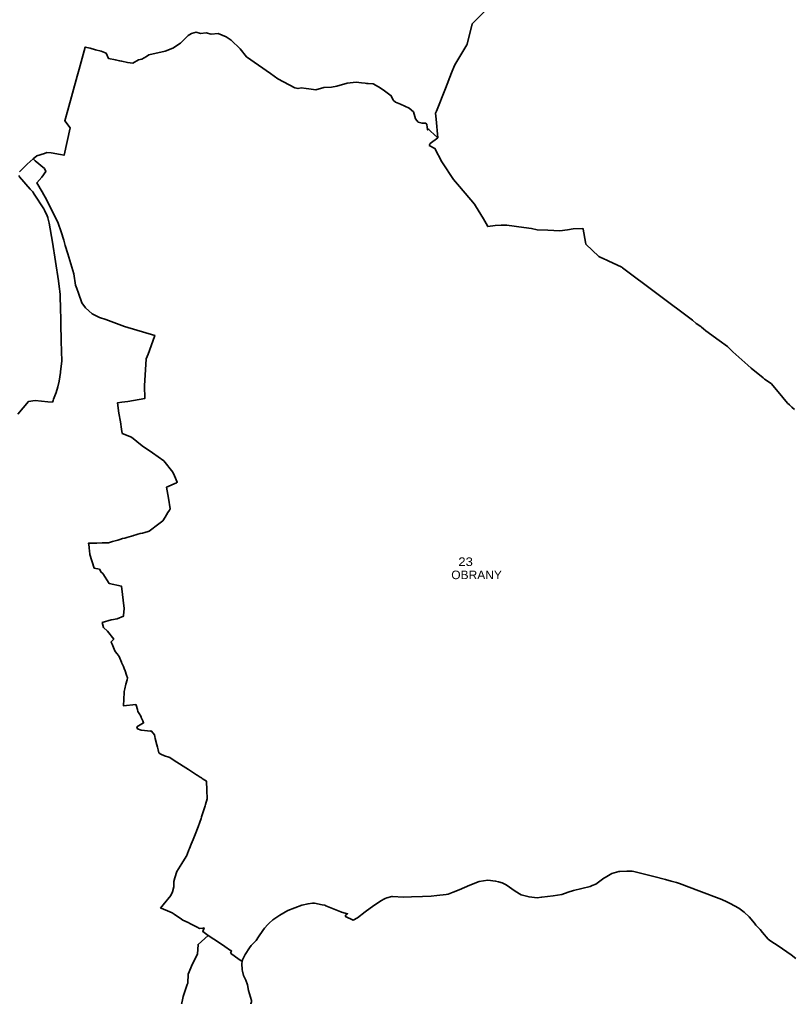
# Model space of a CAD drawing. Extents: x -610940 to -588976, y -1170376 to -1149800.
# Drawn here: x -596331 to -594068, y -1157762 to -1154902 of the extents above; entities that cross this region are included whole.
import ezdxf

# ---------------------------------------------------------------- set-up
doc = ezdxf.new("R2010")
doc.units = 0
doc.header["$LTSCALE"] = 10
doc.layers.add('54', color=7, linetype='Continuous', lineweight=35)
doc.layers.add('55', color=7, linetype='Continuous')
doc.layers.add('56', color=7, linetype='Continuous')

msp = doc.modelspace()

# ---------------------------------------------------------------- linework, layer by layer
at = {"layer": '54'}
for p, q in [((-595762.41, -1157594.1), (-595748.67, -1157602.84)), ((-595713.84, -1157635.74), (-595688.28, -1157653.39)), ((-595712.92, -1157627.4), (-595712.15, -1157627.92)), ((-595712.15, -1157627.92), (-595709.55, -1157629.68)), ((-595688.28, -1157653.39), (-595682.9, -1157657.14)), ((-595840.03, -1157727.17), (-595838.51, -1157722.82))]:
    msp.add_line(p, q, dxfattribs=at)
for points in [[(-594622.71, -1154865.58), (-594646.74, -1154867.4), (-594653.7, -1154868.08), (-594663.98, -1154853.48), (-594711.65, -1154816.59), (-594781.77, -1154806.74), (-594846.26, -1154824.79), (-594858.48, -1154826.3), (-594863.26, -1154826.82), (-594903.94, -1154831.02), (-594929.78, -1154848.3), (-594932.22, -1154849.74), (-594956.48, -1154865.5), (-595005.69, -1154915.44), (-595020.68, -1154974.54), (-595021.77, -1154976.36), (-595054.03, -1155029.88), (-595058.01, -1155036.7), (-595066.38, -1155058.3), (-595084.21, -1155104.14), (-595110.63, -1155170.57), (-595112.96, -1155176.16), (-595111.29, -1155193.92), (-595106.51, -1155248.2)], [(-596291.2, -1155310.54), (-596280.54, -1155301.63), (-596258.1, -1155294.06), (-596251.39, -1155292.04), (-596238.55, -1155292.99), (-596211.27, -1155297.54), (-596200.37, -1155299.52), (-596182.3, -1155219.38), (-596198.45, -1155198.44), (-596189.99, -1155167.8), (-596162.57, -1155068.28), (-596156.82, -1155047.96), (-596138.47, -1154982.87), (-596124.3, -1154986.33), (-596108.39, -1154990.68), (-596091.89, -1154995.25), (-596077.47, -1155000.86), (-596070.23, -1155016.7), (-596050.36, -1155020.63), (-596038.12, -1155023.05), (-596031.81, -1155024.45), (-596015.28, -1155028.11), (-595999.14, -1155029.96), (-595982.56, -1155020.84), (-595973.11, -1155018.42), (-595959.43, -1155010.19), (-595952.03, -1155005.78), (-595904.23, -1154995.31), (-595882.14, -1154985.89), (-595859.81, -1154971.63), (-595837.26, -1154948.82), (-595827.09, -1154943.49), (-595813.62, -1154939.23), (-595801.5, -1154943.07), (-595784.24, -1154941.5), (-595769.85, -1154945.18), (-595749.95, -1154943.61), (-595726.33, -1154952.78), (-595711.33, -1154962.31), (-595684.95, -1154987.68)], [(-595684.95, -1154987.68), (-595666.32, -1155011.48), (-595596.6, -1155060.17), (-595574.65, -1155075.7), (-595524.52, -1155102.28), (-595515.65, -1155104.45), (-595506.9, -1155102.74), (-595492.23, -1155103.97), (-595483.78, -1155104.78), (-595463.07, -1155107.98), (-595439.65, -1155101.6), (-595417.28, -1155100.35), (-595402.11, -1155097.01), (-595372.16, -1155088.26), (-595345.87, -1155085.3), (-595329.84, -1155087.61), (-595319.12, -1155089.09), (-595315.54, -1155089.38), (-595310.33, -1155089.63), (-595296, -1155090.79), (-595279.87, -1155099.66), (-595266.83, -1155108.52), (-595242.76, -1155125.34), (-595237.14, -1155138.13), (-595229.82, -1155144.12), (-595216.12, -1155149.68), (-595190.08, -1155162.28), (-595177.37, -1155172.69), (-595171.75, -1155193.4), (-595163.72, -1155202.58), (-595152.3, -1155206.04), (-595141.63, -1155205.77), (-595138.14, -1155209.53), (-595136.34, -1155225.45), (-595134.34, -1155223), (-595132.98, -1155223.93), (-595127.53, -1155228.87), (-595106.51, -1155248.2), (-595129.01, -1155265.67), (-595131.41, -1155270.88)], [(-595131.41, -1155270.88), (-595114.84, -1155279.7), (-595094.36, -1155318.81), (-595092.64, -1155321.94), (-595060.21, -1155371.01), (-595042.84, -1155391.16), (-594999.33, -1155442.6), (-594996.07, -1155447.63), (-594972.71, -1155485.6), (-594961.1, -1155506.62), (-594960.57, -1155508.2), (-594960.34, -1155508.16), (-594938.14, -1155504.89), (-594921.27, -1155504.46), (-594904.71, -1155504.27), (-594854.2, -1155511.28), (-594831.9, -1155514.3), (-594815.28, -1155517.66), (-594784.75, -1155519.37), (-594749.59, -1155520.83), (-594726.53, -1155517.84), (-594710.55, -1155515.48), (-594681.56, -1155514.41), (-594681.2, -1155516.39), (-594674.37, -1155554.04), (-594673.17, -1155559.9), (-594635.12, -1155596.05), (-594627.59, -1155599.72), (-594624.56, -1155601.19), (-594607.96, -1155608.96), (-594567.32, -1155627.63), (-594566.05, -1155628.92), (-594360.67, -1155782.72), (-594350.44, -1155792.19), (-594335.86, -1155801.35), (-594334.2, -1155802.65), (-594334.07, -1155802.86), (-594328.79, -1155807.37), (-594321.34, -1155813.46), (-594282.56, -1155841.51)], [(-596325.07, -1155342.61), (-596308.81, -1155326.09), (-596291.2, -1155310.54), (-596288.32, -1155312.94), (-596284.83, -1155315.86), (-596257.81, -1155338.49), (-596254.31, -1155347.05), (-596265.78, -1155364.28), (-596280.68, -1155380.54), (-596264.37, -1155406.58), (-596250.91, -1155431.27), (-596217.44, -1155498.26), (-596209.3, -1155524.26), (-596201.61, -1155548.12), (-596196.96, -1155563.4), (-596189.55, -1155587.77), (-596171.91, -1155646.6), (-596167.45, -1155679.57), (-596163.72, -1155690.2), (-596158.62, -1155703.81), (-596148.31, -1155732.09), (-596137.86, -1155745.95), (-596118.06, -1155764.2), (-596097.19, -1155774.78), (-596078.59, -1155780.07), (-596023.64, -1155800.84), (-595934.97, -1155827.22), (-595935.86, -1155830.14), (-595954.74, -1155881.73), (-595959.93, -1155895.5), (-595965.34, -1155974.68), (-595963.98, -1156011.52), (-596014.39, -1156020.21), (-596031.38, -1156022.87), (-596044.5, -1156024.49), (-596040.02, -1156054.74), (-596035.86, -1156080.19), (-596032.11, -1156101.68), (-596030.19, -1156114.12), (-596003.01, -1156124.98)], [(-596335.77, -1156057.31), (-596305.22, -1156020.75), (-596285.15, -1156017.78), (-596248.23, -1156021.71), (-596247.78, -1156021.73), (-596234.86, -1156022.39), (-596232.73, -1156017.21), (-596231.17, -1156013.42), (-596223.66, -1155994.21), (-596218.92, -1155977.78), (-596214.74, -1155960.8), (-596210.99, -1155935.47), (-596210.6, -1155932.43), (-596207.54, -1155902.78), (-596208.21, -1155873.22), (-596208.86, -1155844.32), (-596209.62, -1155791.68), (-596210.2, -1155775.3), (-596210.73, -1155752.29), (-596212.09, -1155708.45), (-596212.92, -1155697.82), (-596213.58, -1155691.75), (-596216.89, -1155667), (-596234.47, -1155554.53), (-596243.82, -1155497.99), (-596248.24, -1155482.4), (-596248.5, -1155481.76), (-596250.41, -1155477.12), (-596257.93, -1155459.95), (-596260.3, -1155456.55), (-596288.09, -1155413.34), (-596292.51, -1155407.16), (-596299.5, -1155398.78), (-596330.74, -1155362.38), (-596333.08, -1155358.65)], [(-596331.48, -1155348), (-596325.07, -1155342.61)], [(-594282.56, -1155841.51), (-594258.71, -1155859.27), (-594257.02, -1155860.52), (-594242.94, -1155874.64), (-594198.4, -1155914.04), (-594188.7, -1155922.62)], [(-594188.7, -1155922.62), (-594154.18, -1155951.32), (-594150.21, -1155954.83), (-594130.74, -1155968.26), (-594109.44, -1155992.57), (-594082.81, -1156025.06), (-594077.04, -1156030.42), (-594069.79, -1156037.15), (-594062.47, -1156043.95)], [(-596003.01, -1156124.98), (-595971.71, -1156150.59), (-595941.87, -1156170.76), (-595908.77, -1156193.8), (-595881.78, -1156227.19), (-595877.19, -1156237.92), (-595869.07, -1156256.87), (-595871.7, -1156258.1), (-595900.67, -1156271.62), (-595895.2, -1156303.54), (-595889.81, -1156335), (-595892.21, -1156338.79), (-595896.55, -1156345.61), (-595900.81, -1156352.31), (-595904.89, -1156358.74), (-595911.89, -1156369.75), (-595922.93, -1156378.12), (-595951.89, -1156400.09), (-595954.23, -1156400.74), (-595964.58, -1156403.64), (-595971.01, -1156405.44), (-595977.79, -1156407.33), (-595984.29, -1156409.15), (-595990.96, -1156411.01), (-595997.12, -1156412.73), (-595999.58, -1156413.42), (-596003.44, -1156414.53), (-596010.05, -1156416.42), (-596016.59, -1156418.29), (-596022.86, -1156420.09), (-596029.49, -1156421.99), (-596037.54, -1156424.3), (-596043.22, -1156426.03), (-596058.59, -1156430.71), (-596070.8, -1156434.26), (-596088.61, -1156434.52), (-596104.93, -1156434.75), (-596120.1, -1156434.98), (-596126.92, -1156435.07), (-596127.49, -1156435.08)], [(-596127.49, -1156435.08), (-596128.67, -1156435.1), (-596127.47, -1156445.78), (-596126.87, -1156451.14), (-596126.31, -1156456.98), (-596125.23, -1156468.21), (-596112.97, -1156507.9), (-596097.11, -1156511.09), (-596091.89, -1156520.24), (-596087.23, -1156524.3), (-596068.2, -1156553.37), (-596032.13, -1156561.23), (-596024.7, -1156626.4), (-596026.2, -1156646.52), (-596026.34, -1156648.46), (-596045.26, -1156656.6), (-596061.69, -1156659.42), (-596062.4, -1156659.54), (-596088.72, -1156666.99), (-596085.6, -1156682.49), (-596073.59, -1156692.96), (-596055.03, -1156716.14), (-596059.18, -1156720.21), (-596059.7, -1156720.75), (-596061.04, -1156722.38), (-596062.89, -1156724.27), (-596063.14, -1156724.52), (-596062.86, -1156724.88), (-596060.18, -1156731.01), (-596053.6, -1156745.46), (-596050.55, -1156752.13), (-596045.3, -1156759.42), (-596039.6, -1156767.32), (-596037.66, -1156771.82), (-596032.4, -1156783.99), (-596032.33, -1156784.14), (-596027.07, -1156796.3), (-596024.54, -1156802.16), (-596022.05, -1156808.91), (-596017.55, -1156821.98)], [(-596017.55, -1156821.98), (-596014.78, -1156829.48), (-596016.1, -1156834.94), (-596019.33, -1156848.35), (-596022.61, -1156861.97), (-596024.32, -1156869.06), (-596024.7, -1156875.39), (-596025.32, -1156888.71), (-596025.5, -1156891.77), (-596026.65, -1156911.32), (-596026.48, -1156911.3), (-595990.41, -1156907.58), (-595989.87, -1156909.15), (-595986, -1156921.9), (-595984.26, -1156927.53), (-595978.86, -1156937.03), (-595978.22, -1156938.23), (-595975.26, -1156943.74), (-595974.42, -1156945.79), (-595970.39, -1156955.48), (-595967.95, -1156961.37), (-595987.13, -1156972.96), (-595985.78, -1156979.13), (-595974.88, -1156982.33), (-595965.14, -1156983.72), (-595947.65, -1156985.18), (-595945.45, -1156984.56), (-595939.77, -1156991.67), (-595936.35, -1156996.59), (-595935.31, -1157000.74), (-595933.65, -1157007.38), (-595929.07, -1157025.69), (-595927.21, -1157032.3), (-595924.87, -1157040.14), (-595923.21, -1157048.48), (-595919.55, -1157052.11), (-595915.29, -1157054), (-595908.58, -1157056.98), (-595906.76, -1157057.79), (-595894.07, -1157061.27)], [(-595894.07, -1157061.27), (-595891.38, -1157062.9), (-595878.57, -1157070.96), (-595877.9, -1157071.36), (-595836.8, -1157097.82), (-595824.81, -1157105.55), (-595813.29, -1157112.97), (-595811.43, -1157114.16), (-595801.72, -1157120.32), (-595799.85, -1157121.51), (-595798.26, -1157122.51), (-595796.49, -1157123.63), (-595793.4, -1157125.79), (-595783.76, -1157131.75), (-595783.13, -1157158.58), (-595782.06, -1157183.42), (-595786.52, -1157200.39), (-595787.49, -1157204.31), (-595788.21, -1157207.03), (-595796.91, -1157233.61), (-595797.82, -1157235.8), (-595798.34, -1157237.37), (-595799.72, -1157241.44), (-595803.32, -1157252.22), (-595807.74, -1157265.05), (-595816.49, -1157288.21), (-595822.19, -1157302.46), (-595828.15, -1157316.21), (-595833.25, -1157328.49), (-595834.98, -1157332.75), (-595836.07, -1157335.4), (-595842.51, -1157350.98), (-595843.54, -1157352.56), (-595855.68, -1157372.6), (-595860.29, -1157380.21), (-595870.2, -1157396.5), (-595876, -1157414.84), (-595879.36, -1157425.47), (-595879.44, -1157441.52), (-595883.4, -1157455.61)], [(-595241.39, -1157469.88), (-595239.53, -1157469.6), (-595207.1, -1157471.14), (-595183.48, -1157470.13), (-595151.03, -1157469.36), (-595125.9, -1157468.27), (-595109.64, -1157466.81), (-595082.35, -1157463.29), (-595075.74, -1157462.81), (-595071.18, -1157461.13), (-595061.15, -1157457.15), (-595044.14, -1157450.06), (-595012.38, -1157435.88), (-594985.04, -1157425.81), (-594960.12, -1157421.78), (-594937.22, -1157424.32), (-594928.9, -1157426.59), (-594917.58, -1157429.18), (-594906.31, -1157435.53), (-594879.91, -1157453.52), (-594862.45, -1157464.31), (-594839.04, -1157470.56), (-594815.45, -1157473.06), (-594802.57, -1157471.08), (-594802.15, -1157471.02), (-594768.27, -1157467.14), (-594743.67, -1157463.2), (-594725.09, -1157457.25), (-594709.21, -1157451.98), (-594660.38, -1157439.94), (-594654.5, -1157437.32), (-594644.08, -1157433.14), (-594620.11, -1157415.78), (-594616.46, -1157413.51), (-594596.44, -1157402.27), (-594576.31, -1157396.62), (-594573.64, -1157396.44), (-594553.42, -1157394.91), (-594537.27, -1157395.61), (-594532.12, -1157396.19)], [(-594532.12, -1157396.19), (-594473.99, -1157410.78), (-594439.83, -1157419.8), (-594423.26, -1157424.69), (-594415.77, -1157426.62), (-594407.1, -1157428.9), (-594398.93, -1157431.57), (-594342.37, -1157452.71), (-594275.1, -1157478.34), (-594259.96, -1157484.64), (-594250.07, -1157489.8), (-594225.1, -1157503.91), (-594209.72, -1157515.08), (-594194.54, -1157529.08), (-594179.63, -1157547.46), (-594175.15, -1157553.68), (-594167.19, -1157561.16), (-594162.78, -1157566.05), (-594155.71, -1157574.98), (-594138.72, -1157594.24), (-594130.9, -1157600.5), (-594109.78, -1157613.41), (-594072.16, -1157640.36), (-594058.55, -1157650.67)], [(-595883.4, -1157455.61), (-595888.46, -1157466.93), (-595910.87, -1157494.14), (-595918.02, -1157503.21), (-595916.45, -1157503.85), (-595891, -1157514.21), (-595884.6, -1157516.82), (-595878.13, -1157521.2), (-595866, -1157529.49), (-595861.09, -1157532.74), (-595852.58, -1157538.7), (-595837.77, -1157545.74), (-595830.59, -1157549.26), (-595824.39, -1157552.16), (-595810.66, -1157559.64), (-595804.41, -1157563.11), (-595793.03, -1157561.67), (-595790.14, -1157561.35), (-595794.73, -1157572.26), (-595778.65, -1157583.76)], [(-595679.28, -1157659.71), (-595679.1, -1157659.38), (-595678, -1157654.44), (-595670.55, -1157638.76), (-595657.96, -1157619.42), (-595652.55, -1157613.34), (-595648.89, -1157608.77), (-595638.28, -1157598.54), (-595631.79, -1157587.74), (-595618.3, -1157569.1), (-595614.05, -1157562.53), (-595604.05, -1157551.14), (-595600.21, -1157547.19), (-595589.9, -1157538.16), (-595569.39, -1157523.94), (-595545.84, -1157510.42), (-595524.94, -1157502.17), (-595504.91, -1157495.3), (-595486.05, -1157490.48), (-595472.96, -1157489.15), (-595467.64, -1157489.38), (-595445.32, -1157493.43), (-595436.78, -1157495.23), (-595434.49, -1157496.46), (-595400.42, -1157510.68), (-595390.26, -1157514.24), (-595388.1, -1157514.9), (-595370.98, -1157519.86), (-595370.78, -1157519.91), (-595376.62, -1157524.36), (-595376.43, -1157528.15), (-595354.58, -1157538.59), (-595341.44, -1157531.8), (-595319.15, -1157514.38), (-595293.56, -1157495.63), (-595271.52, -1157481.46), (-595264.22, -1157476.92), (-595260.89, -1157475.35), (-595255.69, -1157473.38), (-595241.39, -1157469.88)], [(-595824.32, -1157666.86), (-595809.7, -1157638.69), (-595808.36, -1157609.87), (-595778.65, -1157583.76), (-595762.41, -1157594.1)], [(-595748.67, -1157602.84), (-595729.87, -1157615.92), (-595712.92, -1157627.4)], [(-595709.55, -1157629.68), (-595711.27, -1157631.92), (-595713.84, -1157635.74)], [(-595838.51, -1157722.82), (-595837.06, -1157696.38), (-595824.32, -1157666.86)], [(-595682.9, -1157657.14), (-595679.28, -1157659.71), (-595680.51, -1157665.23), (-595679.36, -1157683.95), (-595678.27, -1157688.38), (-595674.83, -1157700.4), (-595669.2, -1157712.66), (-595668.51, -1157714.33)], [(-595887.18, -1157974.98), (-595885.15, -1157969.15), (-595878.46, -1157949.97), (-595864.39, -1157915.54), (-595863.38, -1157911.89), (-595857.45, -1157890.31), (-595852.45, -1157871.79), (-595851.39, -1157842.37), (-595842.87, -1157815.92), (-595857.78, -1157790.59), (-595852.27, -1157762.24), (-595840.03, -1157727.17)], [(-595668.51, -1157714.33), (-595663.78, -1157727.69), (-595660.49, -1157744.84), (-595652.35, -1157773.96), (-595652.13, -1157778.23), (-595655.88, -1157789.62), (-595662.83, -1157798.94), (-595682.66, -1157812.17), (-595691.38, -1157820.17), (-595700.01, -1157832.84), (-595703.09, -1157836.25), (-595708.63, -1157839.88), (-595719.19, -1157844.48), (-595732.1, -1157848.66), (-595744.93, -1157851.7), (-595762.37, -1157859.95), (-595775.67, -1157870.03), (-595781.94, -1157876.76), (-595783.11, -1157879.36), (-595784.26, -1157894.5)]]:
    msp.add_lwpolyline(points, dxfattribs=at)

# ---------------------------------------------------------------- texts
at = {"layer": '55', "width": 1.05}
msp.add_text('OBRANY ', height=25, dxfattribs=at).set_placement((-595067.03, -1156540.49))
at = {"layer": '56', "width": 1.15}
msp.add_text('23 ', height=25, dxfattribs=at).set_placement((-595046.44, -1156502.01))

doc.saveas('drawing.dxf')
